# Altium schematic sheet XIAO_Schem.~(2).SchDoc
size A; SheetNumber: 1; SheetTotal: 1
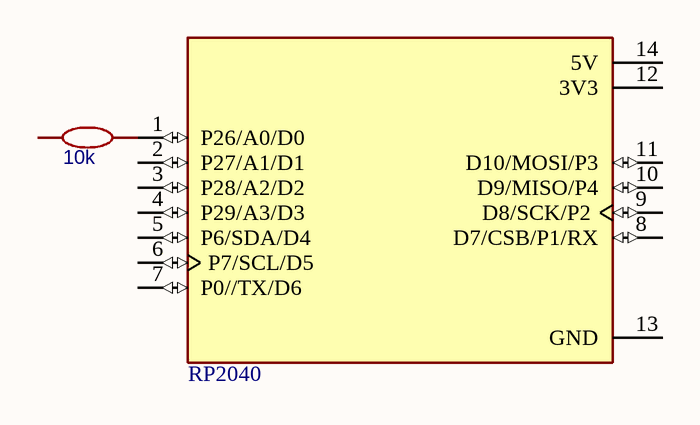
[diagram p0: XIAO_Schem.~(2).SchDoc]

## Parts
10k  10kΩ  [10k]  (value not drawn)
RP2040  102010428  [102010428]  (value not drawn)

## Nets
Net10k_2: 10k.2 RP2040.1(P26/A0/D0)

Not connected (* = marked no-connect by the designer): 10k 1; RP2040 2(P27/A1/D1) 3(P28/A2/D2) 4(P29/A3/D3) 5(P6/SDA/D4) 6(P7/SCL/D5) 7(P0//TX/D6) 8(D7/CSB/P1/RX) 9(D8/SCK/P2) 10(D9/MISO/P4) 11(D10/MOSI/P3) 12(3V3) 13(GND) 14(5V)

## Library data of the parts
10k = 10k: Manufacturer: Tyohm(幸亚电阻); Manufacturer Part: RMC120610K1%N; nameAlias: Value; Contributor: LCSC
RP2040 = 102010428: RP2040 XIAO RP2040 series ARMÂ® CortexÂ®-M0+ MCU 32-Bit Embedded Evaluation Board; MF: Seeed Technology Co., Ltd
